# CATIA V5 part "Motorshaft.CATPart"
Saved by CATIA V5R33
Part number: Motorshaft
Bounding box of the stored display mesh (mm): x -7.25 to 7.25, y -120 to 120, z -7.223 to 7.223
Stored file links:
  D:\PROJECTS\Project 2023\CATIA V5 6R 2023\Resources\Tutorial Files\c12_catia_v5_6r2023_tut\c12Tut1\Motorshaft.CATPart
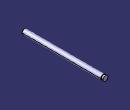
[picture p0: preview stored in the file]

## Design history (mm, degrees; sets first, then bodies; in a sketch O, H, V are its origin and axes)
Body1 (main body)
  Sketch1 on zx-plane, origin (0, 0, 0), H (-1, 0, 0), V (0, 0, 1)
    circle A1 centre (0, 0) radius 7.25
    radius A1 = 7.25
  Pad1: profile Sketch1, direction (0, 1, 0), length 120, mirrored extent
  Sketch2 on yz-plane, origin (0, 0, 0), H (0, 1, 0), V (0, 0, 1)
    line L1 (113.2, 6) -> (115, 6)
    line L2 (115, 6) -> (115, 7.25)
    line L3 (115, 7.25) -> (113.2, 7.25)
    line L4 (113.2, 7.25) -> (113.2, 6)
    reference projected line E1 (120, 7.25) -> (120, -7.25) from edge of Pad1
    reference projected line E2 through (0, 0) direction (1, 0) from axis of face of Pad1 from Sketch1.A1
    distance E1 L2 = 5
    distance H L3 = 7.25
    length L1 = 1.8
    distance L1 E2 = 6
    horizontal: L1 H, L3 H
    vertical: L2 V, L4 V
  Groove1: profile Sketch2, axis axis of face of Pad1, angle 360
